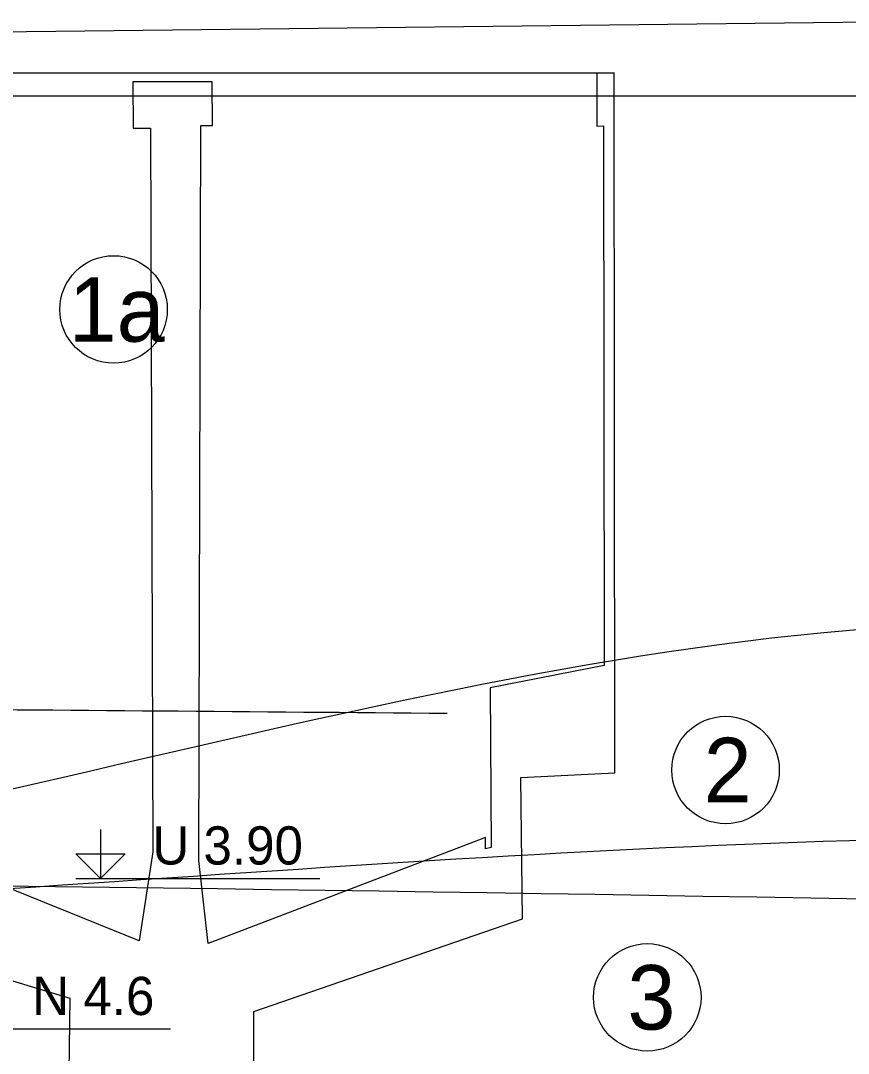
# Model space of a CAD drawing. Extents: x 3042 to 4120, y 576 to 2694.
# Drawn here: x 3245.81 to 3265.06, y 1014.45 to 1038.47 of the extents above; entities that cross this region are included whole.
import ezdxf

# ---------------------------------------------------------------- set-up
doc = ezdxf.new("R2010")
doc.units = 0
for name, color, linetype in [('11', 7, 'Continuous'), ('61', 7, 'Continuous'), ('HPV', 7, 'Continuous'), ('nádrže', 7, 'Continuous'), ('pomocna', 7, 'Continuous'), ('rozhraní', 7, 'Continuous')]:
    doc.layers.add(name, color=color, linetype=linetype)

msp = doc.modelspace()

# ---------------------------------------------------------------- linework, layer by layer
at = {"layer": '11'}
msp.add_line((3229.057, 1038.017), (3268.137, 1038.467), dxfattribs=at)
at = {"layer": '61'}
for p, q in [((3247.091, 1018.517), (3252.763, 1018.517)), ((3244.297, 1015.017), (3249.292, 1015.017))]:
    msp.add_line(p, q, dxfattribs=at)
msp.add_lwpolyline([(3247.662, 1019.66), (3247.662, 1018.517), (3247.091, 1019.089), (3248.234, 1019.089), (3247.662, 1018.517)], dxfattribs=at)
at = {"layer": 'HPV'}
msp.add_spline([(3220.538, 1018.476), (3229.057, 1018.476), (3309.337, 1017.694), (3379.247, 1019.861), (3436.347, 1021.476), (3447.355, 1021.476)], degree=3, dxfattribs=at)
at = {"layer": 'nádrže'}
msp.add_line((3238.989, 1037.25), (3259.609, 1037.25), dxfattribs=at)
for points in [[(3251.233, 1010.73), (3251.23, 1015.425), (3257.481, 1017.581), (3257.436, 1020.866), (3259.627, 1020.978), (3259.609, 1037.25), (3259.209, 1037.239), (3259.21, 1036.017), (3259.364, 1036.021), (3259.378, 1023.469), (3256.722, 1022.953), (3256.751, 1019.235), (3256.62, 1019.21), (3256.618, 1019.467), (3250.167, 1017.002), (3249.949, 1018.932), (3249.994, 1036.03), (3250.264, 1036.03), (3250.261, 1037.044), (3248.416, 1037.044), (3248.42, 1035.969), (3248.825, 1035.969), (3248.884, 1019.139), (3248.565, 1017.07), (3241.914, 1019.755)], [(3239.045, 1036.031), (3239.15, 1021.129), (3241.25, 1021.129), (3241.25, 1017.457), (3246.946, 1015.73), (3246.925, 1014.021)]]:
    msp.add_lwpolyline(points, dxfattribs=at)
at = {"layer": 'pomocna'}
msp.add_line((3207.007, 1036.717), (3306.049, 1036.717), dxfattribs=at)
at = {"layer": 'rozhraní'}
for centre in [(3247.967, 1031.751), (3262.2, 1021.04), (3260.38, 1015.753)]:
    msp.add_circle(centre, 1.25, dxfattribs=at)
for points in [[(3220.533, 1018.149), (3229.057, 1018.017), (3268.137, 1024.467), (3309.571, 1019.217), (3311.623, 1019.217)], [(3255.722, 1022.353), (3229.057, 1022.517), (3220.352, 1022.517)], [(3220.435, 1017.54), (3229.057, 1017.517), (3268.137, 1019.467), (3309.337, 1018.217), (3311.82, 1018.217)]]:
    msp.add_spline(points, degree=3, dxfattribs=at)

# ---------------------------------------------------------------- texts
at = {"layer": '61'}
for s, p in [('U 3.90', (3248.869, 1018.841)), ('N 4.6', (3246.075, 1015.341))]:
    msp.add_text(s, height=0.889, dxfattribs=at).set_placement(p)
at = {"layer": 'rozhraní'}
for s, p in [('1a', (3246.923, 1031.001)), ('2', (3261.692, 1020.29)), ('3', (3259.918, 1015.003))]:
    msp.add_text(s, height=1.5, dxfattribs=at).set_placement(p)

doc.saveas('drawing.dxf')
